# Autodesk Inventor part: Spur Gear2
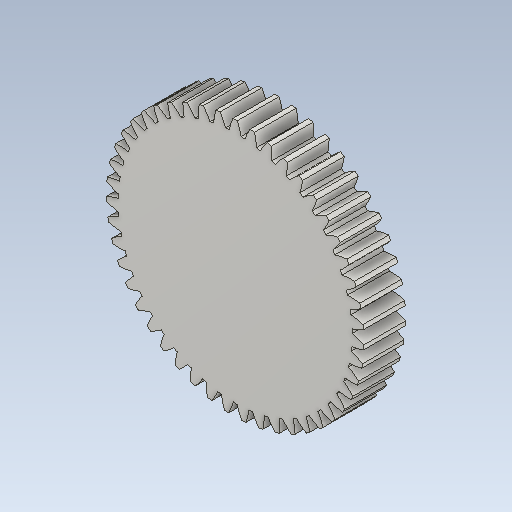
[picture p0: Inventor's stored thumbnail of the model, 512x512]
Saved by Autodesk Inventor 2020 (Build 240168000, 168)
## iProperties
Created: 2019-09
Part Number: Spur Gear2
Material: Steel
Document SubType Name: Modeling
Designer: user
Categories: <?xml version="1.0" encoding="UTF-16"?> <MemberInstance><Categories><FamilyTemplate><FamilyTemplateParameter ValueType="xs:double" Id="1" ObjectReferenceKey="da
Density: 1 g/cm^3
Appearance: Steel
CustomPartVersion: 1
Author: user
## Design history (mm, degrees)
sketch "Sketch1"
  geometry: C1 r 30.875 at (0, 0)
  constraints: 1 centre point
  dimensions: "d0" = 61.75 diameter of C1 (= da_da)
extrude "Extrusion1" new body sketch "Sketch1" distance "d1" = 10 (= da_b); taper "d2" = 0 deg
workplane "Work Plane2"
sketch "Sketch2"
  geometry: C1 r 30.875 at (0, 0) reference; C2 r 29.543 at (0, 0)
  constraints: 1 centre point, 1 coincident
  dimensions: "d3" = 59.08571 diameter of C2 (= da_dw)
feature "Pitch Diameter" sketch "Sketch2" dims "d4" = 10, "d5" = 0
workplane "Work Plane8"
workplane "Work Plane9"
feature "Spur Gear" dims "da_b" = 10, "da_d" = 58.75, "da_aw" = 44, "da_da" = 61.75, "da_df" = 56.14567, "da_dw" = 59.08571, angle "da_beta" = 0 deg, "da_lefttooth" = 0, "da_righttooth" = 0
body "Solid1"
body "Srf1"
other parameters: "d16" = 44 (= da_aw), "d17" = 0, "d34" = 0.66842 (computed from da_z), "d39" = 0, "d41" = 0, "d43" = 44 (= da_aw), "d46" = 44 (= da_aw), "d47" = 0, "d48" = 0
